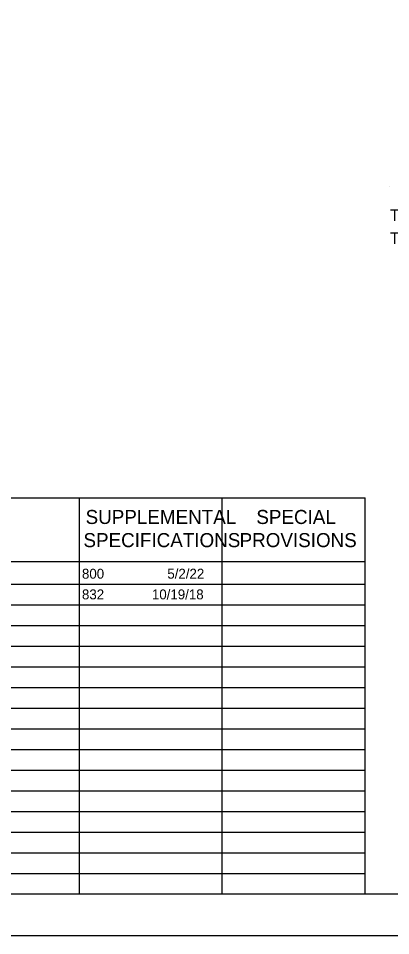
# Model space of a CAD drawing. Extents: x 0 to 84, y -106 to 22.
# Drawn here: x 20.51 to 25.01, y 0 to 11.09 of the extents above; entities that cross this region are included whole.
import ezdxf

# ---------------------------------------------------------------- set-up
doc = ezdxf.new("R2010")
doc.units = 0
for name, color, linetype in [('CS-ALGN-CNTR', 7, 'Continuous'), ('CS-ALGN-TEXT', 7, 'Continuous'), ('CS-ANNO', 7, 'Continuous'), ('CS-ANNO-MATC', 7, 'Continuous')]:
    doc.layers.add(name, color=color, linetype=linetype)

msp = doc.modelspace()

# ---------------------------------------------------------------- linework, layer by layer
at = {"layer": 'CS-ALGN-CNTR'}
msp.add_lwpolyline([(0, 0), (34, 0), (34, 22), (0, 22)], close=True, dxfattribs=at)
at = {"layer": 'CS-ALGN-TEXT'}
msp.add_lwpolyline([(1.5, 21.5), (33.5, 21.5), (33.5, 0.5), (1.5, 0.5)], close=True, dxfattribs=at)
at = {"layer": 'CS-ANNO'}
for p, q in [((25, 9.06), (25, 9.06)), ((11.25, 5.292), (24.7, 5.292)), ((21.25, 0.5), (21.25, 5.292)), ((22.975, 0.5), (22.975, 5.292)), ((24.7, 0.5), (24.7, 5.292)), ((11.25, 4.521), (24.7, 4.521)), ((11.25, 4.25), (24.7, 4.25)), ((11.25, 4), (24.7, 4)), ((11.25, 3.75), (24.7, 3.75)), ((11.25, 3.5), (24.7, 3.5)), ((11.25, 3.25), (24.7, 3.25)), ((11.25, 3), (24.7, 3)), ((11.25, 2.75), (24.7, 2.75)), ((11.25, 2.5), (24.7, 2.5)), ((11.25, 2.25), (24.7, 2.25)), ((11.25, 2), (24.7, 2)), ((11.25, 1.75), (24.7, 1.75)), ((11.25, 1.5), (24.7, 1.5)), ((11.25, 1.25), (24.7, 1.25)), ((11.25, 1), (24.7, 1)), ((11.25, 0.75), (24.7, 0.75))]:
    msp.add_line(p, q, dxfattribs=at)

# ---------------------------------------------------------------- texts
for s, p in [('THE MAKING OF THIS IMPROVEMENT WILL NOT REQUIRE', (25, 8.64)), ('THE CLOSING TO TRAFFIC OF THE HIGHWAY.', (25, 8.361))]:
    msp.add_text(s, height=0.14, dxfattribs=at).set_placement(p)
at = {"layer": 'CS-ANNO-MATC'}
for s, height, p in [('SUPPLEMENTAL', 0.17, (21.324, 4.976)), ('SPECIAL', 0.17, (23.386, 4.976)), ('SPECIFICATIONS', 0.17, (21.298, 4.696)), ('PROVISIONS', 0.17, (23.184, 4.696)), ('800', 0.12, (21.28, 4.315)), ('5/2/22', 0.12, (22.311, 4.315)), ('832', 0.12, (21.28, 4.065)), ('10/19/18', 0.12, (22.125, 4.065))]:
    msp.add_text(s, height=height, dxfattribs=at).set_placement(p)

doc.saveas('drawing.dxf')
